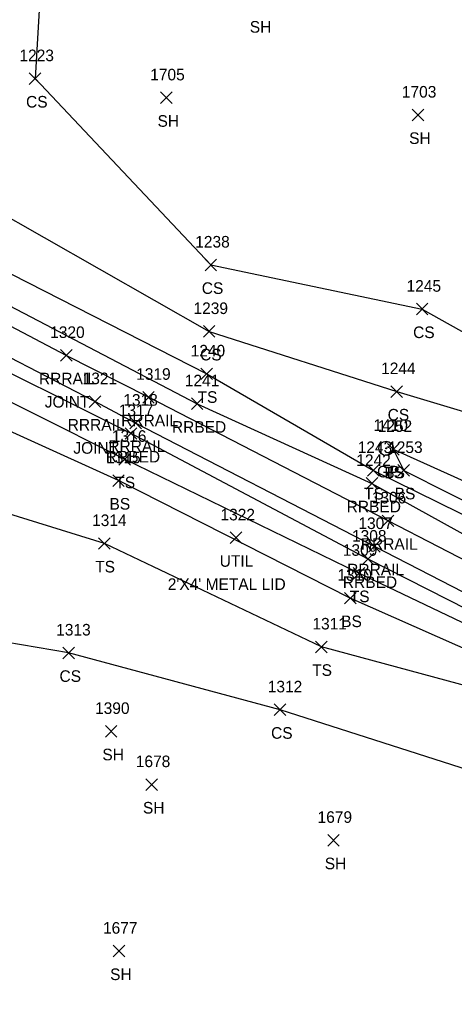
# Model space of a CAD drawing. Extents: x 1443960 to 1446865, y 610387 to 616706.
# Drawn here: x 1446659.6 to 1446734.6, y 611000.1 to 611170.6 of the extents above; entities that cross this region are included whole.
import ezdxf

# ---------------------------------------------------------------- set-up
doc = ezdxf.new("R2010")
doc.units = 0
for name, color, linetype in [('L_A', 7, 'Continuous'), ('L_I', 7, 'Continuous'), ('L_TIC', 7, 'Continuous'), ('LELB', 7, 'Continuous'), ('R_A', 7, 'Continuous'), ('R_C', 7, 'Continuous'), ('R_I', 7, 'Continuous'), ('R_TIC', 7, 'Continuous'), ('RGP', 7, 'Continuous'), ('RR', 7, 'Continuous'), ('RRB', 7, 'Continuous'), ('U_A', 7, 'Continuous'), ('U_C', 7, 'Continuous'), ('U_I', 7, 'Continuous'), ('UDEFAULT', 7, 'Continuous')]:
    doc.layers.add(name, color=color, linetype=linetype)

msp = doc.modelspace()

# ---------------------------------------------------------------- linework, layer by layer
at = {"layer": 'L_TIC'}
for points in [[(1446661.27, 611159.47), (1446663.27, 611161.47)], [(1446663.27, 611159.47), (1446661.27, 611161.47)], [(1446683.9, 611156.16), (1446685.9, 611158.16)], [(1446685.9, 611156.16), (1446683.9, 611158.16)], [(1446727.3, 611153.19), (1446729.3, 611155.19)], [(1446729.3, 611153.19), (1446727.3, 611155.19)], [(1446691.58, 611127.32), (1446693.58, 611129.32)], [(1446693.58, 611127.32), (1446691.58, 611129.32)], [(1446728.03, 611119.7), (1446730.03, 611121.7)], [(1446730.03, 611119.7), (1446728.03, 611121.7)], [(1446691.29, 611115.85), (1446693.29, 611117.85)], [(1446693.29, 611115.85), (1446691.29, 611117.85)], [(1446690.88, 611108.53), (1446692.88, 611110.53)], [(1446692.88, 611108.53), (1446690.88, 611110.53)], [(1446723.64, 611105.48), (1446725.64, 611107.48)], [(1446725.64, 611105.48), (1446723.64, 611107.48)], [(1446723.05, 611095.52), (1446725.05, 611097.52)], [(1446725.05, 611095.52), (1446723.05, 611097.52)], [(1446723.05, 611095.52), (1446725.05, 611097.52)], [(1446725.05, 611095.52), (1446723.05, 611097.52)], [(1446676.7, 611093.8), (1446678.7, 611095.8)], [(1446678.7, 611093.8), (1446676.7, 611095.8)], [(1446719.61, 611091.87), (1446721.61, 611093.87)], [(1446721.61, 611091.87), (1446719.61, 611093.87)], [(1446724.85, 611091.88), (1446726.85, 611093.88)], [(1446726.85, 611091.88), (1446724.85, 611093.88)], [(1446675.65, 611090.11), (1446677.65, 611092.11)], [(1446677.65, 611090.11), (1446675.65, 611092.11)], [(1446673.23, 611079.27), (1446675.23, 611081.27)], [(1446675.23, 611079.27), (1446673.23, 611081.27)], [(1446717.13, 611074.14), (1446719.13, 611076.14)], [(1446719.13, 611074.14), (1446717.13, 611076.14)], [(1446715.62, 611069.84), (1446717.62, 611071.84)], [(1446717.62, 611069.84), (1446715.62, 611071.84)], [(1446710.65, 611061.43), (1446712.65, 611063.43)], [(1446712.65, 611061.43), (1446710.65, 611063.43)], [(1446667.04, 611060.39), (1446669.04, 611062.39)], [(1446669.04, 611060.39), (1446667.04, 611062.39)], [(1446703.53, 611050.58), (1446705.53, 611052.58)], [(1446705.53, 611050.58), (1446703.53, 611052.58)], [(1446674.39, 611046.86), (1446676.39, 611048.86)], [(1446676.39, 611046.86), (1446674.39, 611048.86)], [(1446681.38, 611037.68), (1446683.38, 611039.68)], [(1446683.38, 611037.68), (1446681.38, 611039.68)], [(1446712.74, 611028.07), (1446714.74, 611030.07)], [(1446714.74, 611028.07), (1446712.74, 611030.07)], [(1446675.72, 611008.95), (1446677.72, 611010.95)], [(1446677.72, 611008.95), (1446675.72, 611010.95)]]:
    msp.add_lwpolyline(points, dxfattribs=at)
at = {"layer": 'LELB'}
for points in [[(1446650.95, 611452.22), (1446651.9, 611426.45), (1446649.87, 611385.11), (1446652.75, 611374.92), (1446649.16, 611347.4), (1446644.4, 611298.29), (1446641.62, 611252.48), (1446636.15, 611208.65), (1446631.11, 611163.63), (1446633.53, 611158.95), (1446637.37, 611162.3), (1446642.9, 611148.76), (1446645.64, 611144.28), (1446654.29, 611138.48), (1446692.29, 611116.85), (1446724.64, 611106.48), (1446767.02, 611093.78), (1446771.54, 611085.7), (1446779.15, 611079.3), (1446804.37, 611061.23), (1446846.91, 611054.82)], [(1446646.01, 611451.43), (1446645.8, 611427.91), (1446642.94, 611384.68), (1446641.12, 611344.07), (1446637.9, 611299.18), (1446633.76, 611254.36), (1446628.53, 611208.76), (1446626.59, 611161.02), (1446631.89, 611151.52), (1446639.4, 611144.52), (1446638.89, 611137.35), (1446641.22, 611135.35), (1446691.88, 611109.53), (1446720.61, 611092.87), (1446765.35, 611070.86), (1446803.04, 611049.45), (1446832.29, 611033.43)], [(1446674.41, 611451.43), (1446673.33, 611423.78), (1446673.4, 611405.75), (1446673.54, 611387.21), (1446676.96, 611378.49), (1446687.51, 611358.67), (1446682.52, 611348.73), (1446672.1, 611338.67), (1446667.43, 611325.36), (1446664.64, 611295.09), (1446664.71, 611246.97), (1446665.06, 611207.83), (1446662.27, 611160.47), (1446692.58, 611128.32), (1446729.03, 611120.7), (1446764.81, 611100.69), (1446774.62, 611095.27), (1446783.7, 611091.47), (1446810.78, 611080.25), (1446852.14, 611066.22)], [(1446830.28, 611016.53), (1446811.1, 611028.66), (1446776.07, 611047.22), (1446765.1, 611052.74), (1446718.13, 611075.14), (1446677.7, 611094.8), (1446645.56, 611110.93), (1446633.09, 611119.85), (1446623.05, 611121.28), (1446619.75, 611099.3), (1446617.85, 611081.96), (1446615.6, 611043.86), (1446614.77, 611002.83), (1446608.04, 610951.6), (1446605.01, 610902.95), (1446601.47, 610861.36)], [(1446829.25, 611014.38), (1446810.48, 611025.97), (1446776.26, 611044.05), (1446764.8, 611049.49), (1446716.62, 611070.84), (1446676.65, 611091.11), (1446643.97, 611105.98), (1446632.65, 611089.9), (1446628.97, 611091.61), (1446629.07, 611084.29), (1446632.07, 611081.47), (1446632.15, 611079.98), (1446631.66, 611078.24), (1446628.85, 611073.01), (1446626.96, 611043.36), (1446621.65, 611002.83), (1446619.79, 610952.72), (1446614.79, 610900.25), (1446612.14, 610862.12)], [(1446724.05, 611096.52), (1446768.29, 611076.57), (1446804.37, 611061.23), (1446839.73, 611044.26)], [(1446724.05, 611096.52), (1446725.85, 611092.88), (1446765.81, 611072.71), (1446804.49, 611053.34), (1446836.35, 611036.87)], [(1446830.53, 611008.19), (1446807.85, 611021.07), (1446773.55, 611038.49), (1446762.29, 611043.61), (1446752.72, 611051.34), (1446711.65, 611062.43), (1446674.23, 611080.27), (1446638.75, 611091.24), (1446639.39, 611078.57), (1446637.85, 611065.45), (1446634.87, 611042.47), (1446630.92, 611001.38), (1446634.24, 610953.7), (1446628.67, 610898.68), (1446624.68, 610861.11)], [(1446826.78, 610994.51), (1446805.32, 611011.95), (1446772.11, 611030.78), (1446756.49, 611034.3), (1446751.93, 611036.39), (1446704.53, 611051.58), (1446668.04, 611061.39), (1446654.45, 611063.68), (1446651.98, 611036.37), (1446649.42, 610997.32), (1446649.97, 610954.25), (1446649.35, 610895.51), (1446645.03, 610860.5)]]:
    msp.add_lwpolyline(points, dxfattribs=at)
at = {"layer": 'R_TIC'}
for points in [[(1446666.65, 611111.72), (1446668.65, 611113.72)], [(1446668.65, 611111.72), (1446666.65, 611113.72)], [(1446680.83, 611104.5), (1446682.83, 611106.5)], [(1446682.83, 611104.5), (1446680.83, 611106.5)], [(1446671.6, 611103.75), (1446673.6, 611105.75)], [(1446673.6, 611103.75), (1446671.6, 611105.75)], [(1446689.22, 611103.37), (1446691.22, 611105.37)], [(1446691.22, 611103.37), (1446689.22, 611105.37)], [(1446678.61, 611100.04), (1446680.61, 611102.04)], [(1446680.61, 611100.04), (1446678.61, 611102.04)], [(1446677.83, 611098.24), (1446679.83, 611100.24)], [(1446679.83, 611098.24), (1446677.83, 611100.24)], [(1446719.36, 611089.64), (1446721.36, 611091.64)], [(1446721.36, 611089.64), (1446719.36, 611091.64)], [(1446722.16, 611083.18), (1446724.16, 611085.18)], [(1446724.16, 611083.18), (1446722.16, 611085.18)], [(1446719.8, 611078.76), (1446721.8, 611080.76)], [(1446721.8, 611078.76), (1446719.8, 611080.76)], [(1446718.7, 611076.58), (1446720.7, 611078.58)], [(1446720.7, 611076.58), (1446718.7, 611078.58)]]:
    msp.add_lwpolyline(points, dxfattribs=at)
at = {"layer": 'RGP'}
msp.add_line((1446722.82, 611096.67), (1446722.82, 611096.67), dxfattribs=at)
for radius in [1.25, 0.0833]:
    msp.add_circle((1446722.82, 611096.67), radius, dxfattribs=at)
at = {"layer": 'RR'}
for points in [[(1446830.8, 611028.51), (1446813.8, 611037.34), (1446780.13, 611054.63), (1446766.6, 611061.72), (1446723.16, 611084.18), (1446681.83, 611105.5), (1446667.65, 611112.72), (1446650.45, 611121.75), (1446635.82, 611129.05), (1446620.36, 611137.27), (1446611.04, 611142.08), (1446598.97, 611148.35), (1446587.47, 611154.32), (1446577.27, 611159.61), (1446545.1, 611176.06), (1446537.95, 611179.67), (1446530.32, 611183.72), (1446472.23, 611213.59), (1446430.68, 611235.02), (1446393.22, 611254.19), (1446353.39, 611274.79), (1446345.67, 611278.8)], [(1446830.61, 611022.91), (1446812, 611032.72), (1446777.67, 611050.48), (1446764.9, 611057.05), (1446720.8, 611079.76), (1446679.61, 611101.04), (1446672.6, 611104.75), (1446648.09, 611117.4), (1446634.05, 611124.73), (1446619.04, 611132.42), (1446610.71, 611136.75), (1446598.39, 611142.94), (1446586.96, 611148.93), (1446576.92, 611154.08), (1446541.41, 611172.48), (1446511.36, 611187.89), (1446469.88, 611209.21), (1446428.54, 611230.42), (1446391.04, 611249.76), (1446351.07, 611270.34), (1446343.04, 611274.54)]]:
    msp.add_lwpolyline(points, dxfattribs=at)
at = {"layer": 'RRB'}
for points in [[(1446632.76, 611134.38), (1446690.22, 611104.37), (1446720.36, 611090.64), (1446766.52, 611065.08), (1446801.87, 611047.12), (1446831.43, 611030.91)], [(1446831.59, 611019.77), (1446811.47, 611030.77), (1446776.48, 611048.4), (1446764.37, 611054.87), (1446719.7, 611077.58), (1446678.83, 611099.24), (1446647.24, 611114.98), (1446628.17, 611124.39)]]:
    msp.add_lwpolyline(points, dxfattribs=at)
at = {"layer": 'UDEFAULT'}
for points in [[(1446695.94, 611080.25), (1446697.94, 611082.25)], [(1446697.94, 611080.25), (1446695.94, 611082.25)]]:
    msp.add_lwpolyline(points, dxfattribs=at)

# ---------------------------------------------------------------- texts
at = {"layer": 'L_A'}
for s, p in [('SH', (1446699.3, 611168.39)), ('CS', (1446660.71, 611155.47)), ('SH', (1446683.39, 611152.16)), ('SH', (1446726.79, 611149.19)), ('CS', (1446691.02, 611123.32)), ('CS', (1446727.47, 611115.7)), ('CS', (1446690.73, 611111.85)), ('TS', (1446690.29, 611104.53)), ('CS', (1446723.08, 611101.48)), ('TS', (1446722.46, 611091.52)), ('BS', (1446722.49, 611091.52)), ('TS', (1446676.11, 611089.8)), ('TS', (1446719.02, 611087.87)), ('BS', (1446724.29, 611087.88)), ('BS', (1446675.1, 611086.11)), ('TS', (1446672.64, 611075.27)), ('TS', (1446716.54, 611070.14)), ('BS', (1446715.06, 611065.84)), ('CS', (1446666.48, 611056.39)), ('TS', (1446710.06, 611057.43)), ('CS', (1446702.97, 611046.58)), ('SH', (1446673.87, 611042.86)), ('SH', (1446680.87, 611033.68)), ('SH', (1446712.23, 611024.07)), ('SH', (1446675.21, 611004.95))]:
    msp.add_text(s, height=2, dxfattribs=at).set_placement(p)
at = {"layer": 'L_I'}
for s, p in [('1223', (1446659.57, 611163.47)), ('1705', (1446682.13, 611160.16)), ('1703', (1446725.53, 611157.19)), ('1238', (1446689.89, 611131.32)), ('1245', (1446726.34, 611123.7)), ('1239', (1446689.59, 611119.85)), ('1240', (1446689.1, 611112.53)), ('1244', (1446721.95, 611109.48)), ('1252', (1446721.36, 611099.52)), ('1252', (1446721.36, 611099.52)), ('1316', (1446675.52, 611097.8)), ('1243', (1446717.91, 611095.87)), ('1253', (1446723.16, 611095.88)), ('1315', (1446674.53, 611094.11)), ('1314', (1446672.1, 611083.27)), ('1309', (1446715.35, 611078.14)), ('1310', (1446714.41, 611073.84)), ('1311', (1446710.1, 611065.43)), ('1313', (1446665.91, 611064.39)), ('1312', (1446702.4, 611054.58)), ('1390', (1446672.61, 611050.86)), ('1678', (1446679.64, 611041.68)), ('1679', (1446710.99, 611032.07)), ('1677', (1446673.98, 611012.95))]:
    msp.add_text(s, height=2, dxfattribs=at).set_placement(p)
at = {"layer": 'R_A'}
for s, p in [('RRRAIL', (1446662.94, 611107.72)), ('RRRAIL', (1446667.89, 611099.75)), ('RRRAIL', (1446677.12, 611100.5)), ('RRBED', (1446685.87, 611099.37)), ('RRRAIL', (1446674.9, 611096.04)), ('RRBED', (1446674.47, 611094.24)), ('GP', (1446721.25, 611091.67)), ('RRBED', (1446716.01, 611085.64)), ('RRRAIL', (1446718.45, 611079.18)), ('RRRAIL', (1446716.1, 611074.76)), ('RRBED', (1446715.35, 611072.58))]:
    msp.add_text(s, height=2, dxfattribs=at).set_placement(p)
at = {"layer": 'R_C'}
for p in [(1446663.93, 611103.72), (1446668.87, 611095.75)]:
    msp.add_text('JOINT', height=2, dxfattribs=at).set_placement(p)
at = {"layer": 'R_I'}
for s, p in [('1320', (1446664.87, 611115.72)), ('1321', (1446670.47, 611107.75)), ('1319', (1446679.7, 611108.5)), ('1241', (1446688.09, 611107.37)), ('1318', (1446677.49, 611104.04)), ('1317', (1446676.7, 611102.24)), ('1410', (1446720.61, 611099.67)), ('1242', (1446717.67, 611093.64)), ('1306', (1446720.33, 611087.18)), ('1307', (1446718.03, 611082.76)), ('1308', (1446716.93, 611080.58))]:
    msp.add_text(s, height=2, dxfattribs=at).set_placement(p)
at = {"layer": 'U_A'}
msp.add_text('UTIL', height=2, dxfattribs=at).set_placement((1446694.1, 611076.25))
at = {"layer": 'U_C'}
msp.add_text("2'X4' METAL LID", height=2, dxfattribs=at).set_placement((1446685.15, 611072.25))
at = {"layer": 'U_I'}
msp.add_text('1322', height=2, dxfattribs=at).set_placement((1446694.24, 611084.25))

doc.saveas('drawing.dxf')
